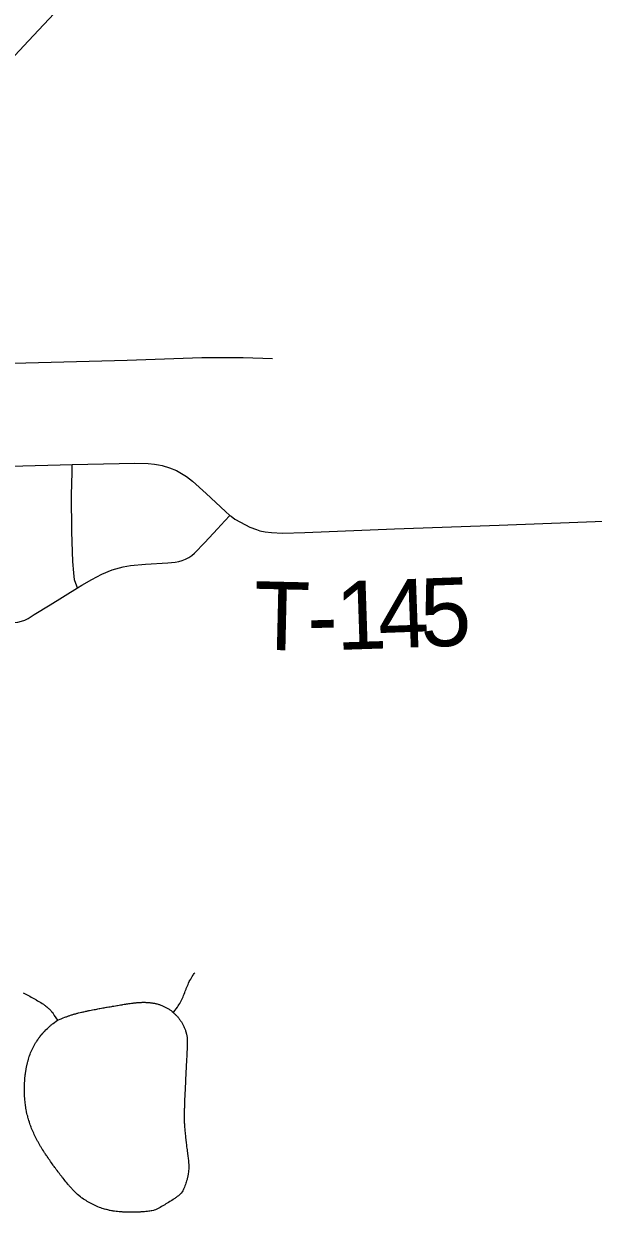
# Model space of a CAD drawing. Extents: x 63.4 to 97.4, y 0.4 to 22.4.
# Drawn here: x 68.383 to 68.856, y 19.881 to 20.868 of the extents above; entities that cross this region are included whole.
import ezdxf

# ---------------------------------------------------------------- set-up
doc = ezdxf.new("R2010")
doc.units = 0
for name, color, linetype in [('GM_X_County_Road', 7, 'Continuous'), ('GM_X_Township_Road', 7, 'Continuous'), ('GM_X_Township_Road_Text', 7, 'Continuous')]:
    doc.layers.add(name, color=color, linetype=linetype)

msp = doc.modelspace()

# ---------------------------------------------------------------- linework, layer by layer
at = {"layer": 'GM_X_County_Road'}
msp.add_lwpolyline([(68.34487, 20.79996), (68.34827, 20.80618), (68.3529, 20.81344), (68.35822, 20.82116), (68.36391, 20.82861), (68.372, 20.83812), (68.3868, 20.85412), (68.43349, 20.90412), (68.45709, 20.92885), (68.52321, 20.99901), (68.53995, 21.01738), (68.54604, 21.02439), (68.55164, 21.03175), (68.5584, 21.04213), (68.56136, 21.04695)], dxfattribs=at)
at = {"layer": 'GM_X_Township_Road'}
for points in [[(68.27204, 20.58459), (68.27861, 20.58467), (68.2973, 20.58491), (68.38453, 20.58667), (68.46862, 20.58893), (68.53079, 20.591), (68.54325, 20.59112), (68.56504, 20.59116), (68.58939, 20.59019)], [(68.24705, 20.49874), (68.25074, 20.49849), (68.25519, 20.49818), (68.27672, 20.49842), (68.31712, 20.49911), (68.34505, 20.49971), (68.38219, 20.50115), (68.41306, 20.5018), (68.42311, 20.50204)], [(68.42759, 20.39978), (68.42623, 20.40337), (68.42514, 20.40623), (68.42432, 20.4123), (68.42375, 20.42153), (68.4227, 20.44618), (68.42243, 20.47703), (68.42294, 20.49551), (68.42311, 20.50204)], [(68.42311, 20.50204), (68.47522, 20.50327), (68.48614, 20.50308), (68.49148, 20.5025), (68.49474, 20.50199), (68.4979, 20.50131), (68.50392, 20.49943), (68.50973, 20.49706), (68.51254, 20.49564), (68.51788, 20.49229), (68.52285, 20.48842), (68.5344, 20.47796), (68.55029, 20.46311), (68.55403, 20.45993)], [(68.42759, 20.39978), (68.43119, 20.40205), (68.43927, 20.40677), (68.44764, 20.411), (68.45633, 20.41454), (68.46231, 20.41647), (68.46537, 20.41724), (68.47157, 20.41825), (68.48399, 20.41935), (68.5026, 20.42051), (68.50869, 20.42093), (68.51162, 20.42149), (68.51446, 20.42236), (68.51725, 20.42349), (68.51996, 20.42487), (68.52245, 20.42652), (68.52477, 20.42843), (68.53334, 20.43728), (68.54376, 20.44872), (68.54984, 20.45536), (68.55403, 20.45993)], [(68.55403, 20.45993), (68.55496, 20.45914), (68.55824, 20.45684), (68.56269, 20.45425), (68.57053, 20.45021), (68.57607, 20.44804), (68.57896, 20.44708), (68.58331, 20.44625), (68.58862, 20.4457), (68.59779, 20.44524), (68.61634, 20.44557), (68.69067, 20.44869), (68.77757, 20.4519), (68.84278, 20.45434), (68.908, 20.45689), (68.94525, 20.45837), (68.95769, 20.45894), (68.96394, 20.45896), (68.97092, 20.45899)], [(68.23999, 20.36268), (68.24815, 20.36315), (68.26673, 20.36424), (68.30708, 20.36534), (68.32563, 20.36632), (68.35031, 20.36887), (68.36889, 20.37039), (68.37501, 20.37085), (68.378, 20.37129), (68.38092, 20.37199), (68.38373, 20.373), (68.38641, 20.37432), (68.39159, 20.37757), (68.40493, 20.3855), (68.42759, 20.39978)], [(68.50713, 20.04686), (68.50755, 20.04746), (68.51039, 20.05136), (68.51108, 20.05238), (68.51175, 20.05342), (68.51238, 20.05449), (68.51298, 20.05556), (68.51355, 20.05666), (68.5141, 20.05777), (68.51461, 20.05889), (68.5151, 20.06002), (68.51557, 20.06117), (68.51603, 20.06232), (68.51649, 20.06347), (68.51694, 20.06462), (68.51717, 20.06519), (68.51761, 20.06634), (68.51784, 20.06692), (68.5183, 20.06807), (68.51878, 20.06921), (68.51927, 20.07034), (68.51978, 20.07147), (68.52032, 20.07258), (68.52089, 20.07368), (68.52148, 20.07476), (68.52211, 20.07583), (68.52276, 20.07688), (68.52343, 20.07791), (68.52378, 20.07843), (68.52448, 20.07945), (68.52485, 20.07995)], [(68.38236, 20.06332), (68.38291, 20.06304), (68.38347, 20.06275), (68.38401, 20.06245), (68.38511, 20.06187), (68.38567, 20.06158), (68.38675, 20.06098), (68.38731, 20.06069), (68.38787, 20.0604), (68.38896, 20.05981), (68.39004, 20.0592), (68.39059, 20.05891), (68.39114, 20.05861), (68.39222, 20.05799), (68.39277, 20.05769), (68.39332, 20.05739), (68.39438, 20.05676), (68.39492, 20.05645), (68.39546, 20.05614), (68.39652, 20.05549), (68.39706, 20.05517), (68.3981, 20.0545), (68.39862, 20.05416), (68.39914, 20.05381), (68.40015, 20.0531), (68.40065, 20.05273), (68.40115, 20.05235), (68.40212, 20.05158), (68.4026, 20.05118), (68.40352, 20.05035), (68.40397, 20.04991), (68.40441, 20.04947), (68.40525, 20.04856), (68.40566, 20.04809), (68.40605, 20.04761), (68.40644, 20.04712), (68.40718, 20.04612), (68.40787, 20.04509), (68.4082, 20.04455), (68.41094, 20.04047)], [(68.41094, 20.04047), (68.41381, 20.04169), (68.41568, 20.04248), (68.4171, 20.04303), (68.41769, 20.04325), (68.41828, 20.04348), (68.41886, 20.04369), (68.41945, 20.04391), (68.42004, 20.04412), (68.42064, 20.04433), (68.42123, 20.04453), (68.42182, 20.04473), (68.42242, 20.04492), (68.42302, 20.0451), (68.42362, 20.04528), (68.42422, 20.04546), (68.42482, 20.04563), (68.42542, 20.04581), (68.42602, 20.04597), (68.42663, 20.04614), (68.42723, 20.04629), (68.42783, 20.04645), (68.42844, 20.04661), (68.42965, 20.04691), (68.43086, 20.04719), (68.43147, 20.04734), (68.43208, 20.04747), (68.43269, 20.04761), (68.4339, 20.04787), (68.43451, 20.048), (68.43512, 20.04812), (68.43573, 20.04825), (68.43634, 20.04838), (68.43695, 20.0485), (68.43756, 20.04862), (68.43878, 20.04887), (68.44, 20.0491), (68.44122, 20.04935), (68.44244, 20.04958), (68.44366, 20.04981), (68.44427, 20.04994), (68.44549, 20.05016), (68.44611, 20.05027), (68.44732, 20.0505), (68.44855, 20.05073), (68.44916, 20.05082), (68.44977, 20.05095), (68.45038, 20.05107), (68.45161, 20.05129), (68.45222, 20.05139), (68.45345, 20.05159), (68.45467, 20.05181), (68.45589, 20.05201), (68.4565, 20.05211), (68.45773, 20.05231), (68.45895, 20.05252), (68.46017, 20.05273), (68.46078, 20.05285), (68.46201, 20.05304), (68.46323, 20.05325), (68.46446, 20.05346), (68.46507, 20.05356), (68.4663, 20.05376), (68.46691, 20.05386), (68.46753, 20.05396), (68.46814, 20.05406), (68.46876, 20.05416), (68.46937, 20.05425), (68.46999, 20.05434), (68.4706, 20.05444), (68.47122, 20.05452), (68.47246, 20.05469), (68.4737, 20.05485), (68.47432, 20.05492), (68.47494, 20.05499), (68.47557, 20.05505), (68.47619, 20.05511), (68.47682, 20.05517), (68.47744, 20.05522), (68.47806, 20.05527), (68.47869, 20.05531), (68.47932, 20.05534), (68.47995, 20.05538), (68.48058, 20.0554), (68.48121, 20.05542), (68.48184, 20.05543), (68.48247, 20.05544), (68.4831, 20.05543), (68.48373, 20.05543), (68.48436, 20.05541), (68.48499, 20.05538), (68.48563, 20.05534), (68.48626, 20.0553), (68.48689, 20.05525), (68.48752, 20.05519), (68.48815, 20.05511), (68.48878, 20.05504), (68.48941, 20.05495), (68.49004, 20.05485), (68.49067, 20.05475), (68.49129, 20.05463), (68.49191, 20.0545), (68.49253, 20.05436), (68.49315, 20.05421), (68.49377, 20.05405), (68.49438, 20.05387), (68.49499, 20.05368), (68.49559, 20.05348), (68.4962, 20.05327), (68.49679, 20.05305), (68.49739, 20.05282), (68.49798, 20.05259), (68.49857, 20.05233), (68.49915, 20.05207), (68.49972, 20.0518), (68.5003, 20.05152), (68.50087, 20.05124), (68.50143, 20.05094), (68.50199, 20.05063), (68.50254, 20.05031), (68.50309, 20.04996), (68.50362, 20.04962), (68.50415, 20.04926), (68.50468, 20.04888), (68.50519, 20.0485), (68.50569, 20.04811), (68.50619, 20.0477), (68.50713, 20.04686)], [(68.38492, 19.96618), (68.3847, 19.96741), (68.38449, 19.96863), (68.3844, 19.96925), (68.38422, 19.97048), (68.38407, 19.97171), (68.38393, 19.97295), (68.3838, 19.97419), (68.38375, 19.97481), (68.38365, 19.97605), (68.38361, 19.97667), (68.38357, 19.97729), (68.38354, 19.97791), (68.38351, 19.97853), (68.38349, 19.97915), (68.38347, 19.97977), (68.38345, 19.9804), (68.38344, 19.98102), (68.38343, 19.98164), (68.38342, 19.98226), (68.38342, 19.98288), (68.38342, 19.9835), (68.38343, 19.98412), (68.38344, 19.98475), (68.38345, 19.98537), (68.38347, 19.98599), (68.38349, 19.98661), (68.38352, 19.98724), (68.38354, 19.98786), (68.38357, 19.98848), (68.38361, 19.9891), (68.38365, 19.98972), (68.38368, 19.99034), (68.38378, 19.99158), (68.38383, 19.9922), (68.38388, 19.99282), (68.38401, 19.99406), (68.38416, 19.99529), (68.38424, 19.99591), (68.38442, 19.99714), (68.38451, 19.99776), (68.38461, 19.99837), (68.38482, 19.9996), (68.38493, 20.00021), (68.38516, 20.00143), (68.38529, 20.00204), (68.38542, 20.00265), (68.38555, 20.00326), (68.38568, 20.00386), (68.38596, 20.00508), (68.38626, 20.00628), (68.38642, 20.00688), (68.38675, 20.00808), (68.38711, 20.00928), (68.38749, 20.01046), (68.38769, 20.01105), (68.38812, 20.01222), (68.38857, 20.01338), (68.38905, 20.01452), (68.3893, 20.01509), (68.38981, 20.01622), (68.39035, 20.01734), (68.39063, 20.0179), (68.39092, 20.01845), (68.3915, 20.01955), (68.39181, 20.02009), (68.39243, 20.02116), (68.39276, 20.0217), (68.39309, 20.02223), (68.39341, 20.02275), (68.39376, 20.02328), (68.39445, 20.02431), (68.3948, 20.02482), (68.39552, 20.02583), (68.39589, 20.02633), (68.39627, 20.02683), (68.39703, 20.02781), (68.39743, 20.02829), (68.39783, 20.02877), (68.39863, 20.02971), (68.39946, 20.03064), (68.39988, 20.0311), (68.40031, 20.03155), (68.40118, 20.03244), (68.40162, 20.03288), (68.40251, 20.03375), (68.40342, 20.0346), (68.40388, 20.03502), (68.4048, 20.03585), (68.40528, 20.03625), (68.40576, 20.03665), (68.40623, 20.03705), (68.40672, 20.03743), (68.40722, 20.03782), (68.41094, 20.04047)], [(68.50713, 20.04686), (68.50761, 20.04642), (68.50807, 20.04598), (68.50852, 20.04554), (68.50897, 20.04509), (68.50941, 20.04464), (68.50985, 20.04418), (68.51028, 20.04371), (68.5107, 20.04323), (68.51111, 20.04274), (68.51152, 20.04225), (68.51191, 20.04174), (68.51229, 20.04123), (68.51266, 20.04071), (68.51302, 20.04018), (68.51337, 20.03965), (68.51372, 20.03911), (68.51405, 20.03857), (68.51438, 20.03803), (68.51469, 20.03747), (68.515, 20.03691), (68.5153, 20.03635), (68.51558, 20.03578), (68.51586, 20.0352), (68.51612, 20.03462), (68.51637, 20.03404), (68.51661, 20.03344), (68.51684, 20.03284), (68.51706, 20.03224), (68.51726, 20.03163), (68.51745, 20.03101), (68.51802, 20.02893), (68.51847, 20.02627), (68.51858, 20.02481), (68.51865, 20.02233), (68.51861, 20.01955), (68.51851, 20.01735), (68.51849, 20.01673), (68.51847, 20.01611), (68.51838, 20.01425), (68.51829, 20.01238), (68.51826, 20.01176), (68.51819, 20.01052), (68.51815, 20.0099), (68.51809, 20.00865), (68.51806, 20.00803), (68.51799, 20.00679), (68.51792, 20.00555), (68.51788, 20.00493), (68.51784, 20.00431), (68.51781, 20.00369), (68.51778, 20.00307), (68.51774, 20.00245), (68.5177, 20.00183), (68.51768, 20.0012), (68.51765, 20.00058), (68.51761, 19.99996), (68.51758, 19.99934), (68.51755, 19.99872), (68.51752, 19.9981), (68.51749, 19.99748), (68.51746, 19.99686), (68.51743, 19.99623), (68.51741, 19.99561), (68.51738, 19.99499), (68.51735, 19.99437), (68.51732, 19.99375), (68.51728, 19.99313), (68.51725, 19.99251), (68.5172, 19.99127), (68.51718, 19.99064), (68.51716, 19.99002), (68.51714, 19.9894), (68.51711, 19.98878), (68.51709, 19.98816), (68.51706, 19.98753), (68.51704, 19.98691), (68.51701, 19.98629), (68.51698, 19.98567), (68.51695, 19.98505), (68.51692, 19.98443), (68.51685, 19.98319), (68.51682, 19.98257), (68.51679, 19.98195), (68.51675, 19.98133), (68.51671, 19.98071), (68.51668, 19.98008), (68.51664, 19.97946), (68.51661, 19.97884), (68.51658, 19.97822), (68.51654, 19.9776), (68.51651, 19.97698), (68.51648, 19.97636), (68.51646, 19.97573), (68.51643, 19.97511), (68.51641, 19.97449), (68.51639, 19.97387), (68.51637, 19.97325), (68.51636, 19.97263), (68.51634, 19.97201), (68.51632, 19.97139), (68.5163, 19.97076), (68.51628, 19.97014), (68.51626, 19.96952), (68.51623, 19.9689), (68.51622, 19.96828), (68.5162, 19.96766), (68.51618, 19.96704), (68.51617, 19.96641), (68.51614, 19.96579), (68.51612, 19.96517), (68.5161, 19.96455), (68.51608, 19.96393), (68.51607, 19.9633), (68.51607, 19.96268), (68.51605, 19.96206), (68.51605, 19.96144), (68.51605, 19.96019), (68.51607, 19.95957), (68.51608, 19.95895), (68.51609, 19.95833), (68.5161, 19.95771), (68.51612, 19.95709), (68.51614, 19.95647), (68.51617, 19.95584), (68.51619, 19.95522), (68.51622, 19.9546), (68.51625, 19.95398), (68.51629, 19.95336), (68.51633, 19.95274), (68.51637, 19.95212), (68.51641, 19.9515), (68.51651, 19.95026), (68.51656, 19.94964), (68.51661, 19.94902), (68.51666, 19.94839), (68.51678, 19.94716), (68.51691, 19.94592), (68.51704, 19.94468), (68.5171, 19.94406), (68.51724, 19.94283), (68.51738, 19.94159), (68.51751, 19.94036), (68.51759, 19.93974), (68.51773, 19.9385), (68.51789, 19.93727), (68.51796, 19.93665), (68.51812, 19.93542), (68.51829, 19.93418), (68.51845, 19.93295), (68.51861, 19.93172), (68.51878, 19.93049), (68.51894, 19.92926), (68.51901, 19.92863), (68.51911, 19.92802), (68.5192, 19.9274), (68.51936, 19.92617), (68.51943, 19.92555), (68.51958, 19.92432), (68.5197, 19.92308), (68.51975, 19.92246), (68.51979, 19.92184), (68.51983, 19.92122), (68.51986, 19.92059), (68.51989, 19.91936), (68.51989, 19.91873), (68.51988, 19.91811), (68.51986, 19.91749), (68.51984, 19.91687), (68.51976, 19.91563), (68.51971, 19.91501), (68.51965, 19.91439), (68.51948, 19.91316), (68.51939, 19.91254), (68.51916, 19.91132), (68.51903, 19.91071), (68.51889, 19.91011), (68.5186, 19.9089), (68.51843, 19.9083), (68.51826, 19.9077), (68.51808, 19.9071), (68.51769, 19.90592), (68.51749, 19.90533), (68.51707, 19.90417), (68.51686, 19.90358), (68.51664, 19.903), (68.51621, 19.90183), (68.51577, 19.90067), (68.51554, 19.90009), (68.51529, 19.89952), (68.51502, 19.89896), (68.51438, 19.89789), (68.51362, 19.89691), (68.51276, 19.89601), (68.51184, 19.89518), (68.51137, 19.89478), (68.51088, 19.89439), (68.51038, 19.89401), (68.50937, 19.89329), (68.50886, 19.89294), (68.50834, 19.89258), (68.50731, 19.89189), (68.50679, 19.89155), (68.50575, 19.89087), (68.50522, 19.89054), (68.50469, 19.89022), (68.50416, 19.88989), (68.5031, 19.88924), (68.50256, 19.88892), (68.5015, 19.88828), (68.50097, 19.88795), (68.4999, 19.88731), (68.49884, 19.88667), (68.49831, 19.88634), (68.49723, 19.88571), (68.49616, 19.88508), (68.49507, 19.88448), (68.49397, 19.8839), (68.49283, 19.88341), (68.49226, 19.88317), (68.49108, 19.88277), (68.49049, 19.8826), (68.48929, 19.88229), (68.48868, 19.88216), (68.48745, 19.88194), (68.48684, 19.88184), (68.48561, 19.88168), (68.48499, 19.88161), (68.48436, 19.88155), (68.48313, 19.88144), (68.48251, 19.8814), (68.48189, 19.88135), (68.48126, 19.88132), (68.48064, 19.88128), (68.48002, 19.88126), (68.4794, 19.88123), (68.47878, 19.8812), (68.47816, 19.88117), (68.47754, 19.88115), (68.47691, 19.88113), (68.47629, 19.88111), (68.47567, 19.8811), (68.47505, 19.88109), (68.47442, 19.88108), (68.4738, 19.88107), (68.47318, 19.88106), (68.47256, 19.88106), (68.47194, 19.88106), (68.47132, 19.88106), (68.47069, 19.88107), (68.47007, 19.88108), (68.46945, 19.88109), (68.46883, 19.8811), (68.46821, 19.88111), (68.46759, 19.88113), (68.46697, 19.88116), (68.46634, 19.88118), (68.46572, 19.88121), (68.4651, 19.88124), (68.46448, 19.88128), (68.46386, 19.88132), (68.46324, 19.88137), (68.46262, 19.88142), (68.462, 19.88147), (68.46076, 19.88159), (68.45952, 19.88173), (68.45829, 19.88189), (68.45706, 19.88207), (68.45645, 19.88217), (68.45583, 19.88228), (68.45461, 19.88251), (68.454, 19.88263), (68.4534, 19.88277), (68.45279, 19.88291), (68.45158, 19.88321), (68.45098, 19.88337), (68.44979, 19.88371), (68.44919, 19.88389), (68.44801, 19.88427), (68.44742, 19.88447), (68.44683, 19.88468), (68.44567, 19.88511), (68.44451, 19.88557), (68.44337, 19.88606), (68.44224, 19.88657), (68.44167, 19.88684), (68.44111, 19.88711), (68.44055, 19.88738), (68.43944, 19.88794), (68.43889, 19.88823), (68.43779, 19.88881), (68.43725, 19.88912), (68.4367, 19.88941), (68.43616, 19.88972), (68.43562, 19.89004), (68.43456, 19.89068), (68.43403, 19.89101), (68.43298, 19.89168), (68.43247, 19.89203), (68.43146, 19.89275), (68.43095, 19.89312), (68.42996, 19.89386), (68.42899, 19.89465), (68.42851, 19.89504), (68.42757, 19.89585), (68.42665, 19.89668), (68.42619, 19.89711), (68.42528, 19.89796), (68.42441, 19.89884), (68.42397, 19.89929), (68.42312, 19.90019), (68.42269, 19.90065), (68.42187, 19.90157), (68.42105, 19.90251), (68.42064, 19.90298), (68.42025, 19.90346), (68.41984, 19.90394), (68.41944, 19.90441), (68.41865, 19.90538), (68.41788, 19.90635), (68.41709, 19.90731), (68.41631, 19.90828), (68.41554, 19.90925), (68.41516, 19.90975), (68.41438, 19.91071), (68.41362, 19.9117), (68.41324, 19.91219), (68.41247, 19.91317), (68.41171, 19.91416), (68.41135, 19.91466), (68.4106, 19.91565), (68.40985, 19.91665), (68.40948, 19.91715), (68.40911, 19.91765), (68.40874, 19.91815), (68.40802, 19.91916), (68.40765, 19.91966), (68.40729, 19.92017), (68.40657, 19.92118), (68.40585, 19.9222), (68.40514, 19.92322), (68.40443, 19.92424), (68.40372, 19.92526), (68.40336, 19.92578), (68.40301, 19.92629), (68.40232, 19.92732), (68.40196, 19.92783), (68.40162, 19.92835), (68.40093, 19.92939), (68.40059, 19.9299), (68.40024, 19.93042), (68.3999, 19.93094), (68.39922, 19.93198), (68.39855, 19.93303), (68.39822, 19.93356), (68.39756, 19.93461), (68.39723, 19.93513), (68.39691, 19.93567), (68.39658, 19.9362), (68.39595, 19.93727), (68.39532, 19.93835), (68.39472, 19.93943), (68.39442, 19.93997), (68.39412, 19.94052), (68.39353, 19.94162), (68.39325, 19.94217), (68.3927, 19.94329), (68.39242, 19.94385), (68.39189, 19.94496), (68.39163, 19.94553), (68.39112, 19.94667), (68.39062, 19.9478), (68.39013, 19.94895), (68.3899, 19.94953), (68.38966, 19.9501), (68.38943, 19.95068), (68.38898, 19.95184), (68.38876, 19.95242), (68.38834, 19.95359), (68.38793, 19.95476), (68.38773, 19.95535), (68.38753, 19.95594), (68.38716, 19.95713), (68.3868, 19.95832), (68.38662, 19.95892), (68.3863, 19.96012), (68.38614, 19.96072), (68.38584, 19.96193), (68.38555, 19.96314), (68.38529, 19.96435), (68.38516, 19.96496), (68.38492, 19.96618)]]:
    msp.add_lwpolyline(points, dxfattribs=at)

# ---------------------------------------------------------------- texts
at = {"layer": 'GM_X_Township_Road_Text'}
for s, rotation, p in [('4', 2.09267, (68.67787, 20.34925)), ('5', 2.13447, (68.71289, 20.35053)), ('T', 358.6628, (68.57336, 20.34847)), ('1', 1.89346, (68.64267, 20.34808)), ('-', 1.43702, (68.61885, 20.34749))]:
    msp.add_text(s, height=0.05682, rotation=rotation, dxfattribs=at).set_placement(p)

doc.saveas('drawing.dxf')
